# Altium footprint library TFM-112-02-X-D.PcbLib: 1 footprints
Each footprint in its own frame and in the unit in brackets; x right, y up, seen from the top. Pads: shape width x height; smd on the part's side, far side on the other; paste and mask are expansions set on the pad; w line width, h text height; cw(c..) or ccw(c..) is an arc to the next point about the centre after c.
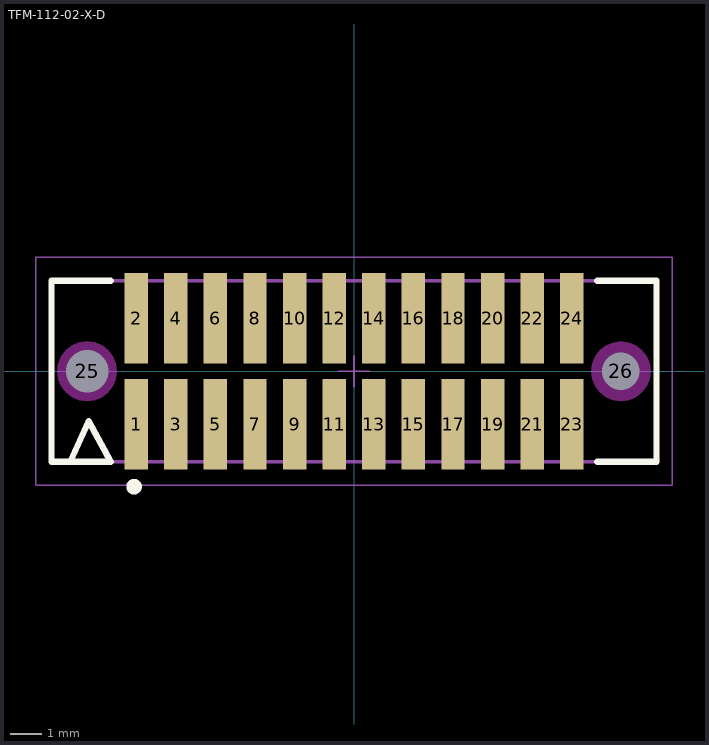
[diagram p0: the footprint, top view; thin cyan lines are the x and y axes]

## TFM-112-02-X-D [mm] "1.27mm pitch, 24 pin, micro terminal strip; double row, SMT"
height 11.18
pads (26):
  rect 0.75x2.9 smd mask+0: 1(-6.985,-1.7) 2(-6.985,1.7) 3(-5.715,-1.7) 4(-5.715,1.7) 5(-4.445,-1.7) 6(-4.445,1.7) 7(-3.175,-1.7) 8(-3.175,1.7) 9(-1.905,-1.7) 10(-1.905,1.7) 11(-0.635,-1.7) 12(-0.635,1.7) 13(0.635,-1.7) 14(0.635,1.7) 15(1.905,-1.7) 16(1.905,1.7) 17(3.175,-1.7) 18(3.175,1.7) 19(4.445,-1.7) 20(4.445,1.7) 21(5.715,-1.7) 22(5.715,1.7) 23(6.985,-1.7) 24(6.985,1.7)
  round 1 hole 1.35 unplated mask+0: 25(-8.55,0)
  round 1 hole 1.2 unplated mask+0: 26(8.55,0)
Top Overlay:
  circle w0.25: c-7.05,-3.7 r0.125
  lines w0.2: -9.1,-2.9 -8.5,-1.6 -7.8,-2.9 -9.7,-2.9 -9.7,2.9 -7.8,2.9 ; 7.8,-2.9 9.7,-2.9 9.7,2.9 7.8,2.9
Keep-Out Layer:
  pour cut-out: 9.511,0 9.478,0.247 9.383,0.477 9.231,0.675 9.033,0.827 8.803,0.922 8.556,0.954 8.309,0.922 8.079,0.827 7.881,0.675 7.73,0.477 7.634,0.247 7.602,0 7.634,-0.247 7.73,-0.477 7.881,-0.675 8.079,-0.827 8.309,-0.922 8.556,-0.954 8.803,-0.922 9.033,-0.827 9.231,-0.675 9.383,-0.477 9.478,-0.247
  pour cut-out: -7.598,0 -7.631,0.248 -7.727,0.479 -7.879,0.677 -8.077,0.83 -8.308,0.925 -8.556,0.958 -8.804,0.925 -9.035,0.83 -9.234,0.677 -9.386,0.479 -9.482,0.248 -9.514,0 -9.482,-0.248 -9.386,-0.479 -9.234,-0.677 -9.035,-0.83 -8.804,-0.925 -8.556,-0.958 -8.308,-0.925 -8.077,-0.83 -7.879,-0.677 -7.727,-0.479 -7.631,-0.248
Mechanical 12:
  lines w0.001: -9.7,-2.9 -9.7,2.9 9.7,2.9 9.7,-2.9 -9.7,-2.9
Mechanical 13:
  lines w0.1: -9.1,-2.9 -8.5,-1.6 -7.8,-2.9 ; -9.7,-2.9 -9.7,2.9 9.7,2.9 9.7,-2.9 -9.7,-2.9
  text ".Designator" at 0,0 h1.52
Mechanical 15:
  lines w0.05: -0.5,0 0.5,0 ; 0,-0.5 0,0.5 ; -10.2,-3.65 -10.2,3.65 10.2,3.65 10.2,-3.65 -10.2,-3.65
